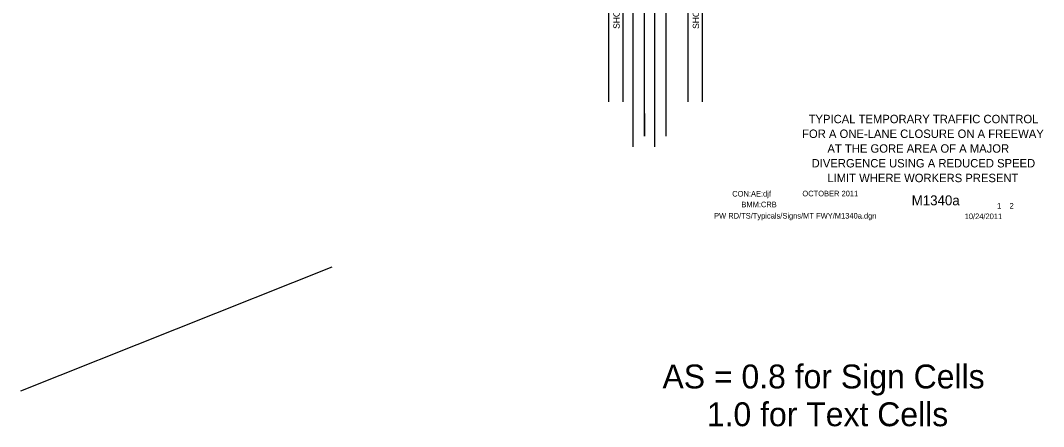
# Model space of a CAD drawing. Extents: x 16303 to 18475, y 5704 to 6974.
# Drawn here: x 16303 to 17435, y 5704 to 6153 of the extents above; entities that cross this region are included whole.
import ezdxf

# ---------------------------------------------------------------- set-up
doc = ezdxf.new("R2010")
doc.units = 0
for name, color, linetype in [('ALI_LEGAL_EX', 7, 'Continuous'), ('BORDER', 7, 'Continuous'), ('BORDER_SIGNAL_WO', 7, 'Continuous'), ('PAVT_EDGE_EX', 7, 'Continuous'), ('TYPICAL_TEXT_DIMEN_PR', 7, 'Continuous')]:
    doc.layers.add(name, color=color, linetype=linetype)

msp = doc.modelspace()

# ---------------------------------------------------------------- linework, layer by layer
at = {"layer": 'ALI_LEGAL_EX'}
for p, q in [((16980.7, 6877), (16980.7, 6013.1)), ((17004.7, 6877), (17004.7, 6013.1)), ((16993.6, 6024.8), (16993.6, 6525.1)), ((17017.6, 6024.8), (17017.6, 6525.1))]:
    msp.add_line(p, q, dxfattribs=at)
for points in [[(16993.6, 6124.8), (16993.6, 6149.8)], [(17017.6, 6124.8), (17017.6, 6149.8)], [(16993.6, 6049.8), (16993.6, 6024.8)]]:
    msp.add_lwpolyline(points, dxfattribs=at)
at = {"layer": 'PAVT_EDGE_EX'}
for p, q in [((16953.6, 6525.1), (16953.6, 6062.7)), ((16969.6, 6525.1), (16969.6, 6062.7)), ((17041.6, 6525.1), (17041.6, 6062.7)), ((17057.6, 6525.1), (17057.6, 6062.7))]:
    msp.add_line(p, q, dxfattribs=at)
at = {"layer": 'TYPICAL_TEXT_DIMEN_PR'}
msp.add_line((16647.8, 5880), (16303.1, 5742.8), dxfattribs=at)

# ---------------------------------------------------------------- texts
at = {"layer": 'BORDER'}
for s, p in [('TYPICAL TEMPORARY TRAFFIC CONTROL', (17175.2, 6039.2)), ('FOR A ONE-LANE CLOSURE ON A FREEWAY', (17168, 6022.9)), ('AT THE GORE AREA OF A MAJOR', (17196, 6006.6)), ('DIVERGENCE USING A REDUCED SPEED', (17178.5, 5990.3)), ('LIMIT WHERE WORKERS PRESENT', (17195.9, 5974))]:
    msp.add_text(s, height=9.3, dxfattribs=at).set_placement(p)
at = {"layer": 'BORDER_SIGNAL_WO'}
for s, height, p in [('CON:AE:djf  ', 6.2, (17090.7, 5958.1)), ('    OCTOBER 2011    ', 6.2, (17159.1, 5958.3)), ('    M1340a   ', 11, (17272.9, 5948.4)), ('BMM:CRB   ', 6.2, (17100.8, 5946.2)), (' 1    2 ', 6.2, (17381.4, 5944.7)), ('PW RD/TS/Typicals/Signs/MT FWY/M1340a.dgn      ', 6.2, (17070.6, 5933.7)), ('10/24/2011    ', 6.2, (17347.9, 5933.1)), ('AS = 0.8 for Sign Cells', 26.424, (17013.5, 5745.8)), ('     1.0 for Text Cells', 26.424, (17013.5, 5704))]:
    msp.add_text(s, height=height, dxfattribs=at).set_placement(p)
at = {"layer": 'TYPICAL_TEXT_DIMEN_PR'}
for p in [(16966.1, 6143.6), (17054, 6143.6)]:
    msp.add_text('SHOULDER', height=7, rotation=90, dxfattribs=at).set_placement(p)

doc.saveas('drawing.dxf')
